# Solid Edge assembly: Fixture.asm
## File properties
Author: Sarvanan
Template: sync ansi assembly.asm
Last saved by: TIET
Revision: 5
Application: Solid Edge
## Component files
end plate.par
disk.par
support pin.par
spacer.par
center pin.par
bolt.par
nut.par
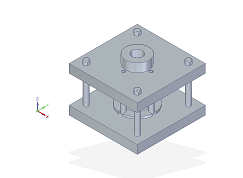
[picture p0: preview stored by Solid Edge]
